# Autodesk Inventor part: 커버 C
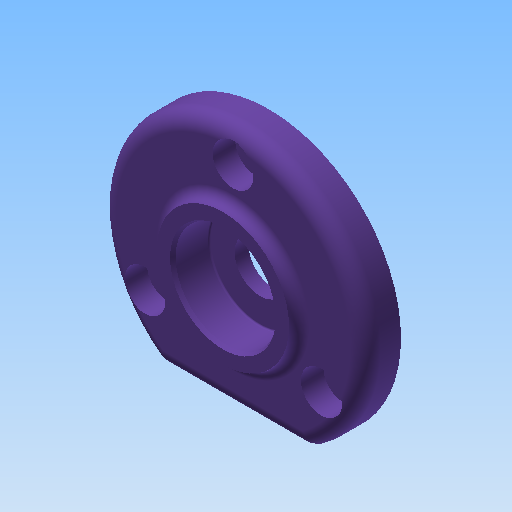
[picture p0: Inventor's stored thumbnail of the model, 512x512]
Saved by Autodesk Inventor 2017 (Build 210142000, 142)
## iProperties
Created: 2020-04
Part Number: 커버 C
Material: 알루미늄 6061
Document SubType Name: Modeling
Designer: mduedu
Density: 2.71 g/cm^3
Mass: 35.2376 g
Surface Area: 62.3739 cm^2
Volume: 13.0028 cm^3
Appearance: 보라색
Author: mduedu
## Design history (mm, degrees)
sketch "스케치1"
  geometry: C1 r 26 at (0, 0); 1 further point
  constraints: 1 centre point, 1 coincident
  dimensions: "d0" = 52 diameter of C1
extrude "돌출1" new body sketch "스케치1" distance "d1" = 7; taper "d2" = 0 deg
sketch "스케치2"
  geometry: L1 (-14.62, -21.5)-(14.62, -21.5); A1 r 26 centre (0, 0) between (-14.62, -21.5) and (14.62, -21.5) reference; 1 further point
  constraints: 2 end point, 2 point on circle, 1 horizontal
  dimensions: "d3" = 21.5 distance from line of L1 point (0, 0)
extrude "돌출2" cut sketch "스케치2" stored distance "d4" = 7; taper "d5" = 0 deg
sketch "스케치6"
  geometry: C1 r 13 at (0, 0); 1 further point
  constraints: 1 centre point, 1 coincident
  dimensions: "d29" = 26 diameter of C1
extrude "돌출5" join sketch "스케치6" distance "d30" = 2; taper "d31" = 0 deg
fillet "모깎기1" dims "d6" = 3
fillet "모깎기2" dims "d7" = 3
fillet "모깎기4" dims "d33" = 2
sketch "스케치3" dims "d8" = 40
  geometry: 3 further points
  constraints: 2 vertical alignment, 1 coincident, 2 other
hole "구멍1" sketch "스케치3" at (0, 20) diameter "d9" = 4.5; stored, may be unused: countersink angle "d13" = 90 deg, drill point angle "d15" = 118 deg; dims "d10" = 6, "d11" = 8, "d12" = 4.4, "d14" = 8
sketch "스케치4"
  geometry: C1 r 14 at (0, 0); 1 further point
  constraints: 1 centre point, 1 coincident
  dimensions: "d19" = 28 diameter of C1
extrude "돌출3" join sketch "스케치4" distance "d20" = 4; taper "d21" = 0 deg
sketch "스케치5"
  geometry: C1 r 12 at (0, 0); 1 further point
  constraints: 1 centre point, 1 coincident
  dimensions: "d22" = 24 diameter of C1
extrude "돌출4" cut sketch "스케치5" distance "d23" = 3; taper "d24" = 0 deg
fillet "모깎기3" dims "d25" = 3
chamfer "모따기1" distance "d26" = 0.5; stored, may be unused: second distance "d27" = 2, angle "d28" = 45 deg
sketch "스케치7"
  geometry: 2 further points
  constraints: 1 coincident
hole "구멍2" sketch "스케치7" at (0, 0) diameter "d34" = 10; stored, may be unused: countersink angle "d38" = 90 deg, drill point angle "d40" = 118 deg; dims "d35" = 6, "d36" = 20, "d37" = 7.3, "d39" = 8
fillet "모깎기5" dims "d41" = 0.3
chamfer "모따기2" distance "d42" = 0.7; stored, may be unused: second distance "d43" = 2, angle "d44" = 30 deg
node "솔리드1"
pattern_circular "원형 패턴1" dims angle "d17" = 360 deg
node "투영된 루프1"
